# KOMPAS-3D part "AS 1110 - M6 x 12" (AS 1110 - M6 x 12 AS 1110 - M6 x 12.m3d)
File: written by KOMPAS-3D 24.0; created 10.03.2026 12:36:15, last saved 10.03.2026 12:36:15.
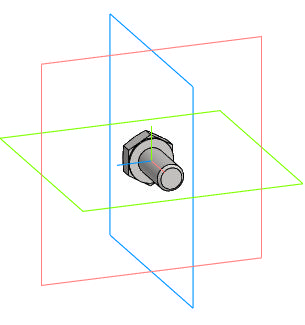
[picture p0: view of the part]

Document properties: Автор: R2D2; Полное имя файла: E:\Работа\Зайцев\BV3232P(4pc)-FP-3WL-F-ISO-H Кран шаровой DN.ru Ду15-100 Ру16\DN40\исходные материалы\AS 1110 - M6 x 12 AS 1110 - M6 x 12.m3d

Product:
- Body: Solid1  | qty 1
- Part/product: AS 1110 - M6 x 12
    Комментарий: Болты и винты   шестигранные точные   метрические ISO
    additional columns: Сталь, мягкая

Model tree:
1. Solid1  (labels: Solid1)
